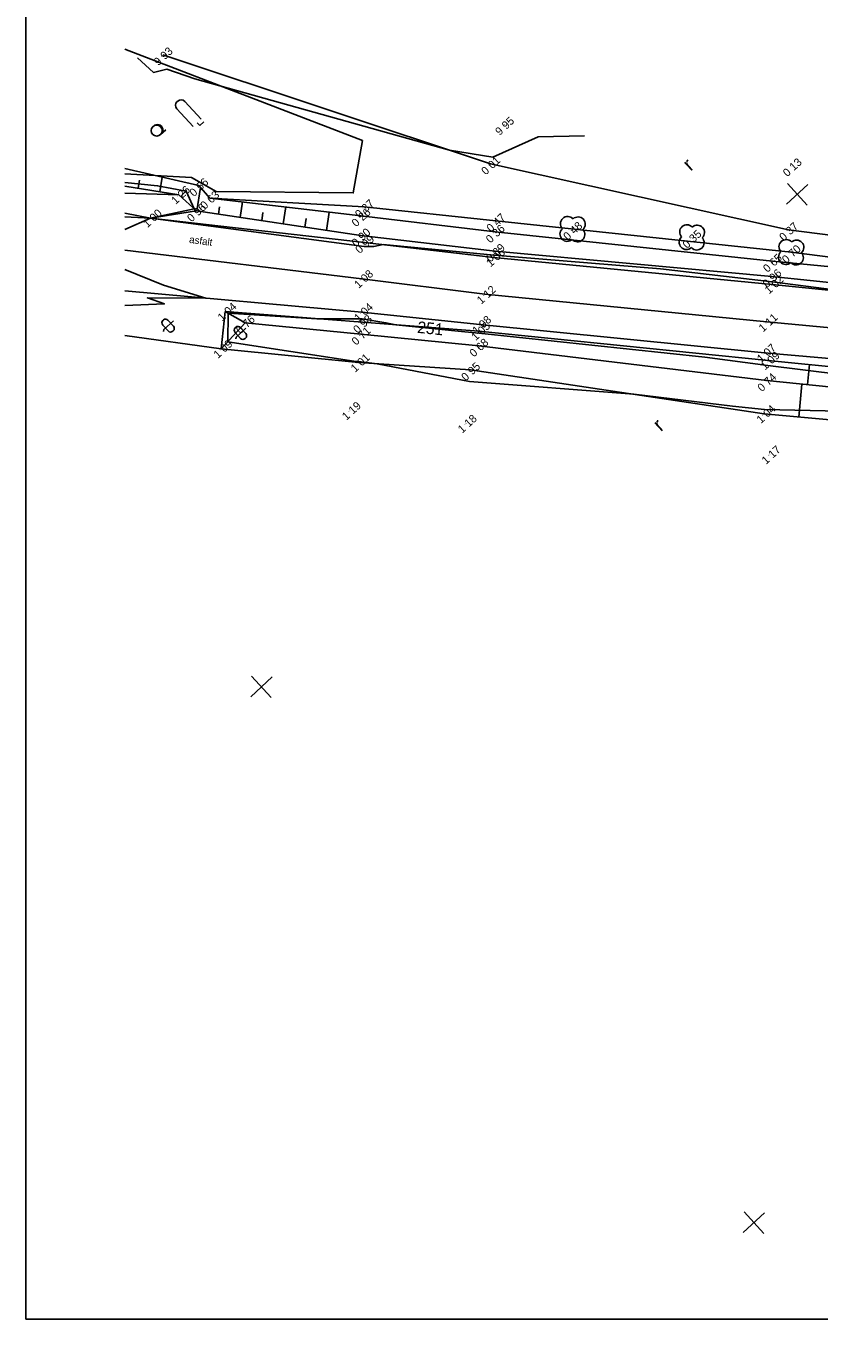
# Model space of a CAD drawing. Extents: x -740053 to -737481, y -1033516 to -1032488.
# Drawn here: x -737902.1 to -737847.6, y -1032955.3 to -1032866.4 of the extents above; entities that cross this region are included whole.
import ezdxf

# ---------------------------------------------------------------- set-up
doc = ezdxf.new("R2010")
doc.units = 0
for name, color, linetype in [('bod-oznac', 7, 'Continuous'), ('bod-vyska', 7, 'Continuous'), ('bod-vyska100', 7, 'Continuous'), ('Contours', 7, 'Continuous'), ('Contours highlighted', 7, 'Continuous'), ('Contours text', 7, 'Continuous'), ('ctv-sit', 7, 'Continuous'), ('Hranice-zelene', 7, 'Continuous'), ('nazvy-bud-povr', 7, 'Continuous'), ('osa-komunikace', 7, 'Continuous'), ('Predmety bez rozlišeni', 7, 'Continuous'), ('rozhraní kultůr', 7, 'Continuous'), ('silnice', 7, 'Continuous'), ('Technické šrafy', 7, 'Continuous'), ('Terenni-hrana', 7, 'Continuous'), ('Znacky-kultury', 7, 'Continuous')]:
    doc.layers.add(name, color=color, linetype=linetype)

# ---------------------------------------------------------------- blocks, each defined once
blk = doc.blocks.new('POINT_DISPLAY')
blk.add_line((0, 0), (0, 0))
blk = doc.blocks.new('p_strom')
for centre, start, end in [((0, 1), 0, 180), ((-1, 0), 90, 270), ((1, 0), 270, 90), ((0, -1), 180, 0)]:
    blk.add_arc(centre, 1, start, end)
at = {"rotation": -180}
blk.add_blockref('POINT_DISPLAY', (0, 0), dxfattribs=at)
blk = doc.blocks.new('p_orna')
blk.add_text('r', height=2).set_placement((0, 0))
blk = doc.blocks.new('p_neplod')
for p, q in [((-0.82, 0), (-0.99, -0.18)), ((1, 0), (-0.82, 0)), ((-0.49, 0.56), (-0.49, -0.55)), ((0.05, 1.01), (-0.04, 1.01)), ((0.5, -0.55), (0.5, 0.56)), ((-0.04, -1), (0.05, -1))]:
    blk.add_line(p, q)
for centre, start, end in [((-0.04, 0.56), 90, 180), ((0.05, 0.56), 0, 90), ((-0.04, -0.55), 180, 270), ((0.05, -0.55), 270, 0)]:
    blk.add_arc(centre, 0.45, start, end)
blk = doc.blocks.new('p_leslis')
for p, q in [((-0.75, 0.5), (-0.75, 3.81)), ((-0.05, 4.51), (0.05, 4.51)), ((0.75, 0.5), (0.75, 3.81)), ((0, 0), (0, 0.5)), ((0, 0), (0.75, 0))]:
    blk.add_line(p, q)
for centre, start, end in [((-0.05, 3.81), 90, 180), ((0.05, 3.81), 0, 90)]:
    blk.add_arc(centre, 0.7, start, end)
blk = doc.blocks.new('p_leskro')
blk.add_line((0, -0.75), (1, -0.75))
blk.add_circle((0, 0), 0.75)
blk.add_arc((0.13, 0), 0.75, 264.8832, 95.1168)
blk = doc.blocks.new('ctvsit')
for p, q in [((0, -2), (0, 2)), ((2, 0), (-2, 0))]:
    blk.add_line(p, q)

msp = doc.modelspace()

# ---------------------------------------------------------------- linework, layer by layer
at = {"layer": 'Contours'}
for points in [[(-737796.34, -1032889.277), (-737808.036, -1032888.253), (-737815.475, -1032887.503), (-737826.627, -1032886.393), (-737847.092, -1032884.477), (-737850.825, -1032883.994), (-737858.487, -1032883.105), (-737869.917, -1032882.163), (-737877.56, -1032881.438), (-737878.192, -1032881.565), (-737878.849, -1032881.569), (-737893.527, -1032879.618), (-737890.546, -1032878.973), (-737891.082, -1032877.779), (-737893.05, -1032877.402), (-737895.298, -1032877.178)], [(-737895.298, -1032879.28), (-737893.527, -1032879.618), (-737895.298, -1032880.408)], [(-737895.298, -1032883.16), (-737892.645, -1032884.234), (-737889.727, -1032885.118), (-737893.745, -1032885.104), (-737892.575, -1032885.516), (-737895.298, -1032885.629)], [(-737879.564, -1032889.437), (-737888.231, -1032888.109), (-737888.202, -1032886.15), (-737882.115, -1032886.532), (-737878.99, -1032886.543), (-737877.36, -1032886.81), (-737876.69, -1032886.948), (-737872.171, -1032887.408), (-737870.979, -1032887.513), (-737855.457, -1032889.179), (-737851.121, -1032889.756), (-737838.556, -1032891.298)], [(-737844.041, -1032892.935), (-737851.352, -1032892.765), (-737853.553, -1032892.55), (-737860.34, -1032891.724), (-737871.616, -1032890.838), (-737877.968, -1032889.629), (-737879.247, -1032889.482), (-737879.564, -1032889.437)]]:
    msp.add_lwpolyline(points, dxfattribs=at)
at = {"layer": 'Contours highlighted'}
msp.add_lwpolyline([(-737863.723, -1032873.96), (-737866.898, -1032874.044), (-737870.013, -1032875.437), (-737872.985, -1032874.951), (-737890.479, -1032870.057), (-737892.407, -1032869.392), (-737893.325, -1032869.614), (-737894.417, -1032868.606)], dxfattribs=at)
at = {"layer": 'Hranice-zelene'}
msp.add_lwpolyline([(-737895.298, -1032868.019), (-737878.971, -1032874.298), (-737879.61, -1032877.886), (-737889.016, -1032877.8), (-737890.71, -1032876.834), (-737895.298, -1032876.58)], dxfattribs=at)
at = {"layer": 'osa-komunikace'}
for p, q in [((-737895.298, -1032881.833), (-737879.018, -1032883.789)), ((-737879.018, -1032883.789), (-737870.562, -1032884.845)), ((-737851.201, -1032886.757), (-737870.562, -1032884.845)), ((-737827.061, -1032888.949), (-737851.201, -1032886.757))]:
    msp.add_line(p, q, dxfattribs=at)
at = {"layer": 'Predmety bez rozlišeni'}
for p, q in [((-737902.097, -1032955.262), (-737902.097, -1032806.762)), ((-737797.097, -1032955.262), (-737902.097, -1032955.262))]:
    msp.add_line(p, q, dxfattribs=at)
at = {"layer": 'rozhraní kultůr'}
for p, q in [((-737892.68, -1032868.394), (-737870.171, -1032875.888)), ((-737849.703, -1032880.423), (-737870.171, -1032875.888)), ((-737826.173, -1032883.501), (-737849.703, -1032880.423)), ((-737888.682, -1032888.598), (-737895.298, -1032887.678))]:
    msp.add_line(p, q, dxfattribs=at)
at = {"layer": 'silnice'}
for p, q in [((-737893.527, -1032879.618), (-737895.298, -1032879.528)), ((-737893.527, -1032879.618), (-737878.827, -1032881.291)), ((-737878.827, -1032881.291), (-737869.953, -1032882.316)), ((-737850.817, -1032884.176), (-737869.953, -1032882.316)), ((-737826.647, -1032886.68), (-737850.817, -1032884.176)), ((-737895.298, -1032884.621), (-737879.022, -1032886.075)), ((-737870.905, -1032886.94), (-737879.022, -1032886.075)), ((-737851.347, -1032888.875), (-737870.905, -1032886.94)), ((-737827.392, -1032890.938), (-737851.347, -1032888.875))]:
    msp.add_line(p, q, dxfattribs=at)
at = {"layer": 'Technické šrafy'}
for p, q in [((-737894.377, -1032877.565), (-737894.288, -1032877.011)), ((-737892.896, -1032877.804), (-737892.734, -1032876.797)), ((-737891.462, -1032878.134), (-737891.068, -1032877.704)), ((-737890.346, -1032879.126), (-737890.103, -1032877.514)), ((-737888.862, -1032879.35), (-737888.786, -1032878.842)), ((-737887.379, -1032879.573), (-737887.219, -1032878.508)), ((-737884.412, -1032880.019), (-737884.237, -1032878.854)), ((-737885.896, -1032879.796), (-737885.812, -1032879.238)), ((-737882.929, -1032880.242), (-737882.838, -1032879.635)), ((-737881.446, -1032880.465), (-737881.256, -1032879.201)), ((-737848.267, -1032889.683), (-737848.404, -1032891.061)), ((-737849.001, -1032893.286), (-737848.795, -1032891.021))]:
    msp.add_line(p, q, dxfattribs=at)
at = {"layer": 'Terenni-hrana'}
for p, q in [((-737895.298, -1032877.907), (-737891.592, -1032878.015)), ((-737878.845, -1032878.849), (-737889.464, -1032878.246)), ((-737869.816, -1032879.809), (-737878.845, -1032878.849)), ((-737869.859, -1032880.572), (-737879.076, -1032879.455)), ((-737849.52, -1032881.966), (-737869.816, -1032879.809)), ((-737879.084, -1032880.821), (-737869.85, -1032881.882)), ((-737850.806, -1032882.577), (-737869.859, -1032880.572)), ((-737850.843, -1032883.63), (-737869.85, -1032881.882)), ((-737826.361, -1032884.937), (-737850.806, -1032882.577)), ((-737826.361, -1032884.937), (-737849.52, -1032881.966)), ((-737826.609, -1032886.13), (-737850.843, -1032883.63)), ((-737887.029, -1032886.806), (-737888.398, -1032886.041)), ((-737878.973, -1032886.777), (-737870.98, -1032887.376)), ((-737870.973, -1032888.388), (-737879.079, -1032887.594)), ((-737851.093, -1032889.402), (-737870.98, -1032887.376)), ((-737851.201, -1032890.777), (-737870.973, -1032888.388)), ((-737879.253, -1032889.547), (-737871.545, -1032890.041)), ((-737827.37, -1032891.759), (-737851.093, -1032889.402)), ((-737851.375, -1032893.07), (-737871.545, -1032890.041)), ((-737827.458, -1032893.185), (-737851.201, -1032890.777)), ((-737828.088, -1032895.19), (-737851.375, -1032893.07))]:
    msp.add_line(p, q, dxfattribs=at)
for points in [[(-737895.298, -1032876.203), (-737890.22, -1032877.379), (-737889.464, -1032878.246), (-737879.076, -1032879.455)], [(-737895.298, -1032877.417), (-737891.592, -1032878.015), (-737890.385, -1032879.121), (-737879.084, -1032880.821)], [(-737890.385, -1032879.121), (-737893.527, -1032879.618)], [(-737888.682, -1032888.598), (-737888.398, -1032886.041), (-737878.973, -1032886.777)], [(-737888.682, -1032888.598), (-737887.029, -1032886.806), (-737879.079, -1032887.594)], [(-737888.682, -1032888.598), (-737879.253, -1032889.547)]]:
    msp.add_lwpolyline(points, dxfattribs=at)

# ---------------------------------------------------------------- block references
at = {"layer": 'bod-oznac', "rotation": 42.589429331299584}
for p in [(-737892.68, -1032868.394), (-737869.222, -1032873.182), (-737870.171, -1032875.888), (-737849.424, -1032875.983), (-737890.22, -1032877.379), (-737891.592, -1032878.015), (-737889.464, -1032878.246), (-737890.385, -1032879.121), (-737878.845, -1032878.849), (-737893.527, -1032879.618), (-737879.076, -1032879.455), (-737869.816, -1032879.809), (-737879.084, -1032880.821), (-737869.859, -1032880.572), (-737864.535, -1032880.379), (-737856.342, -1032880.943), (-737849.703, -1032880.423), (-737878.827, -1032881.291), (-737869.953, -1032882.316), (-737869.85, -1032881.882), (-737850.806, -1032882.577), (-737849.52, -1032881.966), (-737850.843, -1032883.63), (-737879.018, -1032883.789), (-737850.817, -1032884.176), (-737870.562, -1032884.845), (-737888.398, -1032886.041), (-737879.022, -1032886.075), (-737887.029, -1032886.806), (-737878.973, -1032886.777), (-737870.905, -1032886.94), (-737851.201, -1032886.757), (-737879.079, -1032887.594), (-737870.98, -1032887.376), (-737888.682, -1032888.598), (-737870.973, -1032888.388), (-737851.347, -1032888.875), (-737879.253, -1032889.547), (-737851.093, -1032889.402), (-737871.545, -1032890.041), (-737851.201, -1032890.777), (-737879.829, -1032892.821), (-737851.375, -1032893.07), (-737871.869, -1032893.708), (-737850.996, -1032895.846)]:
    msp.add_blockref('POINT_DISPLAY', p, dxfattribs=at)
at = {"layer": 'ctv-sit', "xscale": 0.49999999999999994, "yscale": 0.49999999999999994, "rotation": -137.41057066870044}
for p in [(-737849.105, -1032877.985), (-737885.916, -1032911.822), (-737852.079, -1032948.633)]:
    msp.add_blockref('ctvsit', p, dxfattribs=at)
at = {"layer": 'Znacky-kultury', "yscale": 0.49999999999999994}
for name, p, xscale, rotation in [('p_leslis', (-737890.157, -1032873.263), 0.49999999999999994, 42.589429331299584), ('p_leskro', (-737893.11, -1032873.607), 0.49999999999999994, 42.589429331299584), ('p_orna', (-737856.427, -1032876.438), 0.49999999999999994, 42.589429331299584), ('p_strom', (-737864.535, -1032880.379), 0.4999999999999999, 42.58942933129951), ('p_strom', (-737856.342, -1032880.943), 0.4999999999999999, 42.58942933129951), ('p_strom', (-737849.52, -1032881.966), 0.4999999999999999, 42.58942933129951), ('p_neplod', (-737892.328, -1032887.004), 0.49999999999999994, 42.589429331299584), ('p_neplod', (-737887.359, -1032887.512), 0.49999999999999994, 42.589429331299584), ('p_orna', (-737858.476, -1032894.33), 0.49999999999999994, 42.589429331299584)]:
    msp.add_blockref(name, p, dxfattribs=dict(at, xscale=xscale, rotation=rotation))

# ---------------------------------------------------------------- texts
at = {"layer": 'bod-vyska'}
for s, p in [('9 93', (-737893.003, -1032869.189)), ('9 95', (-737869.545, -1032873.977)), ('0 01', (-737870.504, -1032876.692)), ('0 13', (-737849.786, -1032876.813)), ('1 26', (-737891.809, -1032878.713)), ('0 56', (-737890.553, -1032878.183)), ('0 63', (-737889.806, -1032879.059)), ('0 37', (-737879.178, -1032879.653)), ('1 00', (-737893.744, -1032880.316)), ('0 96', (-737890.718, -1032879.924)), ('0 26', (-737879.408, -1032880.259)), ('0 36', (-737870.191, -1032881.376)), ('0 47', (-737870.149, -1032880.613)), ('0 48', (-737864.868, -1032881.182)), ('0 37', (-737850.036, -1032881.227)), ('0 90', (-737879.416, -1032881.625)), ('0 99', (-737879.16, -1032882.095)), ('0 35', (-737856.675, -1032881.747)), ('0 89', (-737870.183, -1032882.686)), ('1 06', (-737870.17, -1032883.014)), ('0 70', (-737849.853, -1032882.77)), ('0 65', (-737851.148, -1032883.39)), ('1 08', (-737879.235, -1032884.486)), ('0 96', (-737851.176, -1032884.434)), ('1 02', (-737851.034, -1032884.874)), ('1 12', (-737870.808, -1032885.57)), ('1 04', (-737888.615, -1032886.738)), ('0 76', (-737887.361, -1032887.61)), ('0 98', (-737879.306, -1032887.581)), ('1 04', (-737879.239, -1032886.772)), ('1 11', (-737851.447, -1032887.482)), ('0 71', (-737879.411, -1032888.398)), ('1 05', (-737871.197, -1032888.073)), ('1 08', (-737871.122, -1032887.638)), ('1 09', (-737888.899, -1032889.296)), ('0 68', (-737871.316, -1032889.201)), ('1 07', (-737851.564, -1032889.572)), ('1 09', (-737851.31, -1032890.099)), ('1 01', (-737879.47, -1032890.245)), ('0 95', (-737871.878, -1032890.845)), ('0 74', (-737851.533, -1032891.581)), ('1 19', (-737880.075, -1032893.545)), ('1 04', (-737851.592, -1032893.768)), ('1 18', (-737872.115, -1032894.432)), ('1 17', (-737851.242, -1032896.57))]:
    msp.add_text(s, height=0.55, rotation=42.58943, dxfattribs=at).set_placement(p)
at = {"layer": 'bod-vyska100'}
for s, p in [('249 93', (-737892.779, -1032868.531)), ('249 95', (-737869.321, -1032873.319)), ('250 01', (-737870.271, -1032876.025)), ('250 13', (-737849.527, -1032876.123)), ('250 56', (-737890.32, -1032877.517)), ('251 26', (-737891.687, -1032878.148)), ('250 63', (-737889.565, -1032878.385)), ('250 96', (-737890.486, -1032879.258)), ('250 37', (-737878.945, -1032878.987)), ('251 00', (-737893.623, -1032879.751)), ('250 26', (-737879.176, -1032879.593)), ('250 47', (-737869.917, -1032879.946)), ('250 90', (-737879.184, -1032880.958)), ('250 36', (-737869.959, -1032880.71)), ('250 48', (-737864.636, -1032880.516)), ('250 35', (-737856.443, -1032881.08)), ('250 37', (-737849.803, -1032880.56)), ('250 99', (-737878.928, -1032881.429)), ('250 89', (-737869.95, -1032882.019)), ('251 06', (-737870.048, -1032882.449)), ('250 65', (-737850.907, -1032882.716)), ('250 70', (-737849.621, -1032882.104)), ('250 96', (-737850.943, -1032883.768)), ('251 08', (-737879.113, -1032883.922)), ('251 02', (-737850.912, -1032884.309)), ('251 12', (-737870.66, -1032884.981)), ('251 04', (-737888.493, -1032886.174)), ('251 04', (-737879.117, -1032886.207)), ('250 76', (-737887.129, -1032886.944)), ('250 98', (-737879.074, -1032886.915)), ('251 08', (-737871, -1032887.073)), ('251 11', (-737851.299, -1032886.893)), ('250 71', (-737879.179, -1032887.731)), ('251 05', (-737871.075, -1032887.508)), ('251 09', (-737888.777, -1032888.731)), ('250 68', (-737871.074, -1032888.526)), ('251 07', (-737851.442, -1032889.007)), ('251 01', (-737879.348, -1032889.68)), ('251 09', (-737851.188, -1032889.535)), ('250 95', (-737871.646, -1032890.179)), ('250 74', (-737851.301, -1032890.915)), ('251 19', (-737879.927, -1032892.956)), ('251 04', (-737851.47, -1032893.203)), ('251 18', (-737871.967, -1032893.843)), ('251 17', (-737851.094, -1032895.981))]:
    msp.add_text(s, height=0.05, rotation=42.58943, dxfattribs=at).set_placement(p)
at = {"layer": 'Contours text'}
msp.add_text('251', height=0.8, rotation=354.1937, dxfattribs=at).set_placement((-737875.235, -1032887.498))
at = {"layer": 'nazvy-bud-povr'}
msp.add_text('asfalt', height=0.5, rotation=352.06721, dxfattribs=at).set_placement((-737890.902, -1032881.316))

doc.saveas('drawing.dxf')
